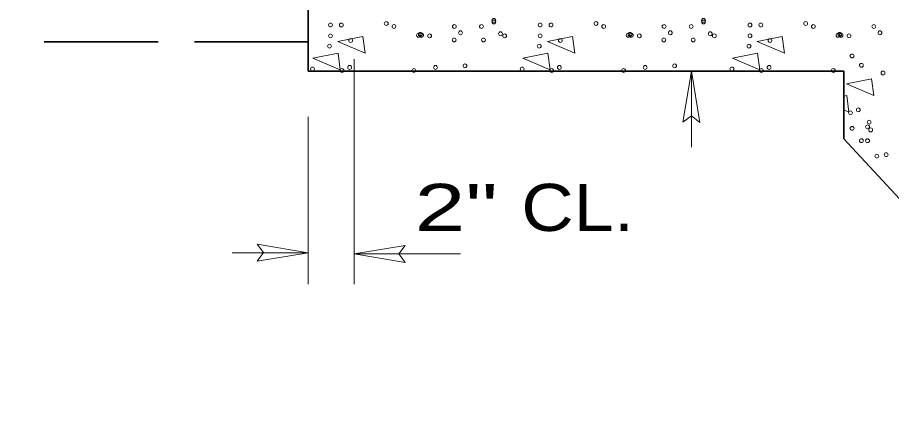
# Model space of a CAD drawing. Extents: x 5.1 to 20.2, y -16.7 to 4.3.
# Drawn here: x 11.185 to 13.579, y -4.277 to -3.2 of the extents above; entities that cross this region are included whole.
import ezdxf
from ezdxf.enums import TextEntityAlignment as Align

# ---------------------------------------------------------------- set-up
doc = ezdxf.new("R2010")
doc.units = 0
doc.header["$LTSCALE"] = 0.052
doc.linetypes.add('LONG_DASHED', pattern=[7.5, 6, -1.5])
for name, color, linetype, lineweight in [('1', 7, 'Continuous', 35), ('10', 7, 'Continuous', 13), ('12', 7, 'Continuous', 53), ('13', 7, 'Continuous', 25), ('6', 7, 'Continuous', 13)]:
    doc.layers.add(name, color=color, linetype=linetype, lineweight=lineweight)

msp = doc.modelspace()

# ---------------------------------------------------------------- linework, layer by layer
at = {"layer": '1'}
for p, q in [((11.98133, -3.34717), (11.98133, -2.96833)), ((11.98133, -3.34717), (13.44808, -3.34717)), ((13.44808, -3.5325), (13.44808, -3.34717)), ((14.24408, -4.38925), (13.44808, -3.5325))]:
    msp.add_line(p, q, dxfattribs=at)
at = {"layer": '1', "linetype": 'LONG_DASHED'}
msp.add_line((11.98158, -3.26633), (10.45483, -3.26633), dxfattribs=at)
at = {"layer": '10'}
for p, q in [((12.10658, -3.314), (12.10658, -3.9305)), ((13.00742, -3.48708), (13.03133, -3.34717)), ((13.05408, -3.48725), (13.03133, -3.34717)), ((13.03133, -3.34717), (13.03133, -3.5555)), ((13.00742, -3.48708), (13.03083, -3.46967)), ((13.05408, -3.48725), (13.03083, -3.46967)), ((11.98133, -3.47217), (11.98133, -3.9305)), ((11.84142, -3.82075), (11.98133, -3.84467)), ((11.84142, -3.82075), (11.85883, -3.84417)), ((12.24667, -3.82442), (12.10658, -3.84717)), ((12.24667, -3.82442), (12.22908, -3.84767)), ((11.98133, -3.84467), (11.773, -3.84467)), ((11.84125, -3.86742), (11.85883, -3.84417)), ((11.84125, -3.86742), (11.98133, -3.84467)), ((12.2465, -3.87108), (12.10658, -3.84717)), ((12.10658, -3.84717), (12.39825, -3.84717)), ((12.2465, -3.87108), (12.22908, -3.84767))]:
    msp.add_line(p, q, dxfattribs=at)
at = {"layer": '6'}
for points in [[(12.06192, -3.2655), (12.13083, -3.252), (12.13683, -3.29758)], [(12.63642, -3.2655), (12.70533, -3.252), (12.71133, -3.29758)], [(13.21092, -3.2655), (13.27983, -3.252), (13.28583, -3.29758)], [(11.99408, -3.31108), (12.063, -3.29758), (12.069, -3.34317)], [(12.56858, -3.31108), (12.6375, -3.29758), (12.6435, -3.34317)], [(13.14308, -3.31108), (13.212, -3.29758), (13.218, -3.34317)], [(13.45533, -3.3815), (13.52425, -3.368), (13.53025, -3.41358)]]:
    msp.add_lwpolyline(points, close=True, dxfattribs=at)
msp.add_lwpolyline([(13.44842, -3.41517), (13.45642, -3.41358), (13.46242, -3.45917), (13.44825, -3.45317)], dxfattribs=at)
for centre in [(12.4895, -3.20783), (12.4895, -3.21208), (13.064, -3.20783), (13.064, -3.21208), (12.04217, -3.2205), (12.07192, -3.2205), (12.19483, -3.21633), (12.21608, -3.22475), (12.3815, -3.22475), (12.45558, -3.22475), (12.61667, -3.2205), (12.64642, -3.2205), (12.76933, -3.21633), (12.79058, -3.22475), (12.956, -3.22475), (13.03008, -3.22475), (13.19117, -3.2205), (13.22092, -3.2205), (13.34383, -3.21633), (13.36508, -3.22475), (13.5305, -3.22475), (12.04217, -3.25025), (12.28325, -3.24875), (12.28817, -3.246), (12.29167, -3.24875), (12.31358, -3.25025), (12.38075, -3.26142), (12.39842, -3.24175), (12.46133, -3.26142), (12.508, -3.2445), (12.51917, -3.25025), (12.61667, -3.25025), (12.85775, -3.24875), (12.86267, -3.246), (12.86617, -3.24875), (12.88808, -3.25025), (12.95525, -3.26142), (12.97292, -3.24175), (13.03583, -3.26142), (13.0825, -3.2445), (13.09367, -3.25025), (13.19117, -3.25025), (13.43225, -3.24875), (13.43717, -3.246), (13.44067, -3.24875), (13.46258, -3.25025), (13.54742, -3.24175), (12.0395, -3.27842), (12.09733, -3.26292), (12.614, -3.27842), (12.67183, -3.26292), (13.1885, -3.27842), (13.24633, -3.26292), (13.47108, -3.30533), (12.41042, -3.3325), (12.98492, -3.3325), (13.4965, -3.33083), (11.99283, -3.341), (12.07342, -3.34525), (12.09467, -3.33675), (12.2705, -3.34525), (12.32983, -3.33675), (12.56733, -3.341), (12.64792, -3.34525), (12.66917, -3.33675), (12.845, -3.34525), (12.90433, -3.33675), (13.14183, -3.341), (13.22242, -3.34525), (13.24367, -3.33675), (13.4195, -3.34525), (13.55592, -3.352), (13.48808, -3.45275), (13.46683, -3.46125), (13.5135, -3.49942), (13.51775, -3.48667), (13.47108, -3.50367), (13.522, -3.50792), (13.4965, -3.53758), (13.5135, -3.53758), (13.53892, -3.58), (13.56442, -3.57575)]:
    msp.add_circle(centre, 0.00525, dxfattribs=at)

# ---------------------------------------------------------------- texts
at = {"layer": '12', "width": 1.15}
msp.add_text('CL.', height=0.129, dxfattribs=at).set_placement((12.56492, -3.78467))
at = {"layer": '13', "width": 1.45}
msp.add_text('2"', height=0.129, dxfattribs=at).set_placement((12.3865, -3.78467), align=Align.CENTER)

doc.saveas('drawing.dxf')
